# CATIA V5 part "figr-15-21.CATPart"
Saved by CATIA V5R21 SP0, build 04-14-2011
Part number: Part1
Bounding box of the stored display mesh (mm): x -81.56 to 85.56, y -36.965 to 25.965, z 0 to 42
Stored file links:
  D:\CATIA V5R21 E-RESOURCES\CATIA-V5R21\catia-v5r21-prt\c15-catia-v5r20-prt\c15-catia-v5r21-figr-15-21.CATPart
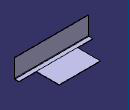
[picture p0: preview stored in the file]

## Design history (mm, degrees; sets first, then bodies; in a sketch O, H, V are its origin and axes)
SheetMetalParameters1: Thickness 1, BendRadius 1, KFactor 0.325257 {= log(min(100,max(20*SheetMetalParameters1.BendRadius,SheetMetalParameters1.Thickness)/SheetMetalParameters1.Thickness))/log(100)/2}, ReliefRadialLength 1, ReliefAxialLength 2, MinimumBendRadius 0
Body1 (main body)
  Sketch1 on xy-plane, origin (0, 0, 0), H (1, 0, 0), V (0, 1, 0)
    line L1 (-46.5596, 25.9646) -> (46.5596, 25.9646)
    line L2 (46.5596, 25.9646) -> (46.5596, -25.9646)
    line L3 (46.5596, -25.9646) -> (-46.5596, -25.9646)
    line L4 (-46.5596, -25.9646) -> (-46.5596, 25.9646)
    horizontal: L1 H, L3 H
    vertical: L2 V, L4 V
    symmetry: L1 L3 H, L4 L2 V
  Wall1: Thickness 1, Profile Sketch1
  d_NewWallOnEdge1: NewWallOnEdge_Edge edge [face of Wall1 | face of Wall1], NewWallOnEdge_Length 42, NewWallOnEdge_HeightLimitOffset 0, NewWallOnEdge_WidthOffset1 39, NewWallOnEdge_WidthOffset2 35, NewWallOnEdge_Angle 90, NewWallOnEdge_BendRadiusValue 1 {= SheetMetalParameters1.BendRadius}, NewWallOnEdge_BendTable SheetMetalParameters1, KFacteur 0.325257 {= log(min(100,max(20*d_NewWallOnEdge1.Radius,SheetMetalParameters1.Thickness)/SheetMetalParameters1.Thickness))/log(100)/2}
